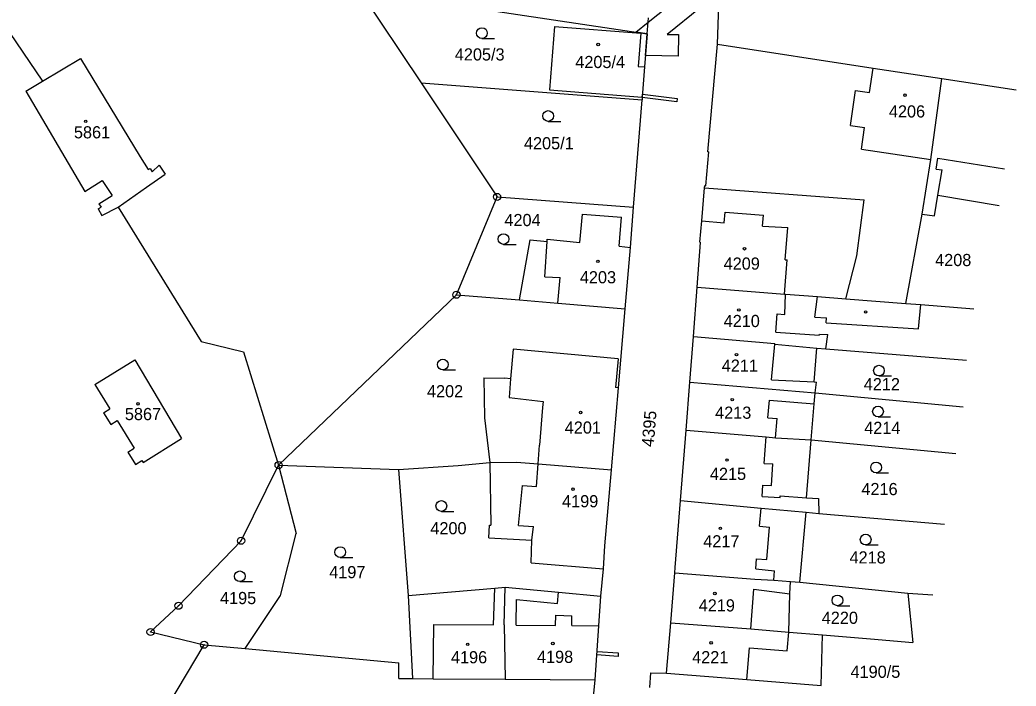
# Model space of a CAD drawing. Extents: x -735092 to -733385, y -1122435 to -1118992.
# Drawn here: x -734332.2 to -734193, y -1120070.4 to -1119977.2 of the extents above; entities that cross this region are included whole.
import ezdxf

# ---------------------------------------------------------------- set-up
doc = ezdxf.new("R2010")
doc.units = 0
for name, color, linetype in [('Vrstva 1', 7, 'Continuous'), ('Vrstva 18', 7, 'Continuous'), ('Vrstva 19', 7, 'Continuous'), ('Vrstva 25', 7, 'Continuous'), ('Vrstva 27', 7, 'Continuous'), ('Vrstva 4', 7, 'Continuous')]:
    doc.layers.add(name, color=color, linetype=linetype)

msp = doc.modelspace()

# ---------------------------------------------------------------- linework, layer by layer
at = {"layer": 'Vrstva 1'}
for points in [[(-734352.91, -1119950.56), (-734329.01, -1119985.77)], [(-734234.74, -1119980.64), (-734234.34, -1119969.65)], [(-734284.75, -1119973.09), (-734276.13, -1119986.04)], [(-734284.75, -1119973.09), (-734244.54, -1119979.16)], [(-734244.54, -1119979.16), (-734244.36, -1119976.92)], [(-734257.49, -1119978.14), (-734258.17, -1119987.02)], [(-734257.49, -1119978.14), (-734245.44, -1119979.06)], [(-734245.44, -1119979.06), (-734245.8, -1119983.74)], [(-734244.54, -1119979.16), (-734244.9, -1119983.81)], [(-734236.05, -1119995.68), (-734234.74, -1119980.64)], [(-734234.74, -1119980.64), (-734212.96, -1119983.97)], [(-734329.01, -1119985.77), (-734323.72, -1119982.6)], [(-734323.72, -1119982.6), (-734315.4, -1119996.37)], [(-734245.8, -1119983.74), (-734244.9, -1119983.81)], [(-734244.9, -1119983.81), (-734245.23, -1119988.02)], [(-734212.96, -1119983.97), (-734203.39, -1119985.4)], [(-734204.89, -1119996.75), (-734203.39, -1119985.4)], [(-734203.39, -1119985.4), (-734193, -1119987.01)], [(-734331.36, -1119987.17), (-734329.01, -1119985.77)], [(-734276.13, -1119986.04), (-734245.26, -1119988.41)], [(-734276.13, -1119986.04), (-734265.52, -1120001.98)], [(-734331.36, -1119987.17), (-734323.11, -1120001.23)], [(-734258.17, -1119987.02), (-734245.23, -1119988.02)], [(-734245.23, -1119988.02), (-734245.26, -1119988.41)], [(-734246.44, -1120003.41), (-734245.26, -1119988.41)], [(-734315.4, -1119996.37), (-734314.27, -1119998.15)], [(-734236.33, -1120000.42), (-734235.91, -1119995.69)], [(-734236.05, -1119995.68), (-734235.91, -1119995.69)], [(-734314.27, -1119998.15), (-734314, -1119997.99)], [(-734314, -1119997.99), (-734313.7, -1119998.47)], [(-734313.7, -1119998.47), (-734312.74, -1119997.56)], [(-734312.74, -1119997.56), (-734311.89, -1119998.78)], [(-734206.13, -1120004.4), (-734204.89, -1119996.75)], [(-734314.49, -1120000.61), (-734311.89, -1119998.78)], [(-734323.11, -1120001.23), (-734320.68, -1119999.7)], [(-734320.68, -1119999.7), (-734319.3, -1120001.79)], [(-734318.48, -1120003.42), (-734314.49, -1120000.61)], [(-734236.9, -1120005.32), (-734236.53, -1120000.73)], [(-734236.53, -1120000.73), (-734236.5, -1120000.4)], [(-734236.53, -1120000.73), (-734214.21, -1120002.37)], [(-734236.5, -1120000.4), (-734236.33, -1120000.42)], [(-734321.15, -1120002.94), (-734319.3, -1120001.79)], [(-734271.19, -1120015.66), (-734265.52, -1120001.98)], [(-734265.52, -1120001.98), (-734246.44, -1120003.41)], [(-734204.38, -1120004.64), (-734203.92, -1120001.75)], [(-734203.92, -1120001.75), (-734195.38, -1120003.16)], [(-734321.23, -1120003.64), (-734320.84, -1120003.43)], [(-734321.23, -1120003.64), (-734320.73, -1120004.56)], [(-734321.15, -1120002.94), (-734320.84, -1120003.43)], [(-734320.73, -1120004.56), (-734318.48, -1120003.42)], [(-734318.48, -1120003.42), (-734306.84, -1120022.19)], [(-734246.88, -1120009.04), (-734246.44, -1120003.41)], [(-734215.26, -1120010.23), (-734214.21, -1120002.37)], [(-734253.93, -1120008.34), (-734253.59, -1120004.4)], [(-734253.59, -1120004.4), (-734248.13, -1120004.8)], [(-734248.47, -1120008.88), (-734248.13, -1120004.8)], [(-734208.42, -1120016.87), (-734206.13, -1120004.4)], [(-734206.13, -1120004.4), (-734204.38, -1120004.64)], [(-734237.19, -1120008.32), (-734236.9, -1120005.32)], [(-734262.36, -1120016.39), (-734260.88, -1120007.96)], [(-734260.88, -1120007.96), (-734258.53, -1120008.19)], [(-734258.53, -1120008.19), (-734258.51, -1120007.89)], [(-734258.51, -1120007.89), (-734253.93, -1120008.34)], [(-734248.47, -1120008.88), (-734246.88, -1120009.04)], [(-734247.6, -1120017.62), (-734246.88, -1120009.04)], [(-734237.54, -1120014.59), (-734237.08, -1120008.33)], [(-734237.19, -1120008.32), (-734237.08, -1120008.33)], [(-734216.78, -1120016.23), (-734215.26, -1120010.23)], [(-734238.07, -1120021.51), (-734237.54, -1120014.59)], [(-734237.54, -1120014.59), (-734225.35, -1120015.57)], [(-734296.04, -1120039.48), (-734271.19, -1120015.66)], [(-734271.19, -1120015.66), (-734262.36, -1120016.39)], [(-734225.35, -1120015.57), (-734225.2, -1120015.58)], [(-734225.2, -1120015.58), (-734220.75, -1120015.92)], [(-734220.75, -1120015.92), (-734216.78, -1120016.23)], [(-734262.36, -1120016.39), (-734257.03, -1120016.82)], [(-734257.03, -1120016.82), (-734247.6, -1120017.62)], [(-734216.78, -1120016.23), (-734208.42, -1120016.87)], [(-734208.42, -1120016.87), (-734206.32, -1120017.04)], [(-734206.32, -1120017.04), (-734198.92, -1120017.65)], [(-734248.54, -1120028.68), (-734247.6, -1120017.62)], [(-734238.57, -1120027.87), (-734238.07, -1120021.51)], [(-734238.07, -1120021.51), (-734226.69, -1120022.46)], [(-734306.84, -1120022.19), (-734300.96, -1120023.64)], [(-734226.7, -1120022.57), (-734226.69, -1120022.46)], [(-734226.7, -1120022.57), (-734220.84, -1120023.11)], [(-734221.2, -1120027.86), (-734220.84, -1120023.11)], [(-734220.84, -1120023.11), (-734219.57, -1120023.23)], [(-734300.96, -1120023.64), (-734296.04, -1120039.48)], [(-734263.29, -1120023.29), (-734263.62, -1120027.4)], [(-734248.61, -1120024.64), (-734263.29, -1120023.29)], [(-734219.57, -1120023.23), (-734199.94, -1120024.79)], [(-734321.72, -1120028.2), (-734316.15, -1120024.74)], [(-734316.15, -1120024.74), (-734309.63, -1120035.75)], [(-734248.61, -1120024.64), (-734248.96, -1120028.64)], [(-734267.38, -1120027.26), (-734264.41, -1120027.34)], [(-734267.38, -1120027.26), (-734267.27, -1120032.87)], [(-734263.62, -1120027.4), (-734264.41, -1120027.34)], [(-734321.72, -1120028.2), (-734319.62, -1120031.59)], [(-734249.52, -1120040.12), (-734248.54, -1120028.68)], [(-734248.54, -1120028.68), (-734248.96, -1120028.64)], [(-734239.1, -1120034.61), (-734238.57, -1120027.87)], [(-734238.57, -1120027.87), (-734221.07, -1120029.38)], [(-734221.2, -1120027.86), (-734220.9, -1120027.88)], [(-734221.07, -1120029.38), (-734220.9, -1120027.88)], [(-734221.2, -1120030.9), (-734221.07, -1120029.38)], [(-734221.07, -1120029.38), (-734200.39, -1120031.34)], [(-734221.61, -1120035.93), (-734221.2, -1120030.9)], [(-734320.52, -1120032.15), (-734319.62, -1120031.59)], [(-734320.52, -1120032.15), (-734319.5, -1120033.81)], [(-734267.27, -1120032.87), (-734266.52, -1120039.14)], [(-734319.5, -1120033.81), (-734318.59, -1120033.25)], [(-734318.59, -1120033.25), (-734316.2, -1120037.11)], [(-734239.87, -1120044.42), (-734239.1, -1120034.61)], [(-734239.1, -1120034.61), (-734227.93, -1120035.55)], [(-734227.93, -1120035.55), (-734226.6, -1120035.66)], [(-734226.6, -1120035.66), (-734221.61, -1120035.93)], [(-734314.97, -1120039.1), (-734309.63, -1120035.75)], [(-734222.3, -1120044.04), (-734221.61, -1120035.93)], [(-734221.61, -1120035.93), (-734201.43, -1120037.84)], [(-734317.09, -1120037.66), (-734316.2, -1120037.11)], [(-734317.09, -1120037.66), (-734316.02, -1120039.39)], [(-734316.02, -1120039.39), (-734315.13, -1120038.84)], [(-734315.13, -1120038.84), (-734314.97, -1120039.1)], [(-734301.28, -1120050.06), (-734296.04, -1120039.48)], [(-734296.04, -1120039.48), (-734279.29, -1120040.09)], [(-734296.04, -1120039.48), (-734293.61, -1120049.04)], [(-734279.29, -1120040.09), (-734270.94, -1120039.55)], [(-734270.94, -1120039.55), (-734266.52, -1120039.14)], [(-734266.52, -1120039.14), (-734262.82, -1120039.05)], [(-734266.52, -1120039.14), (-734266.39, -1120047.9)], [(-734262.82, -1120039.05), (-734259.78, -1120039.29)], [(-734259.78, -1120039.29), (-734249.52, -1120040.12)], [(-734279.29, -1120040.09), (-734277.93, -1120057.7)], [(-734250.44, -1120050.77), (-734249.52, -1120040.12)], [(-734222.3, -1120044.04), (-734220.6, -1120044.16)], [(-734240.63, -1120053.79), (-734239.87, -1120044.42)], [(-734239.87, -1120044.42), (-734228.6, -1120045.5)], [(-734220.6, -1120044.16), (-734220.54, -1120046.24)], [(-734228.6, -1120045.5), (-734222.34, -1120046.07)], [(-734223.22, -1120055.84), (-734222.34, -1120046.07)], [(-734222.34, -1120046.07), (-734220.54, -1120046.24)], [(-734220.54, -1120046.24), (-734203.02, -1120047.74)], [(-734266.67, -1120049.64), (-734266.57, -1120047.89)], [(-734266.57, -1120047.89), (-734266.39, -1120047.9)], [(-734295.79, -1120057.71), (-734293.61, -1120049.04)], [(-734310.02, -1120059.15), (-734301.28, -1120050.06)], [(-734266.67, -1120049.64), (-734260.64, -1120049.96)], [(-734260.77, -1120053.15), (-734260.64, -1120049.96)], [(-734250.66, -1120053.98), (-734250.44, -1120050.77)], [(-734260.77, -1120053.15), (-734250.66, -1120053.98)], [(-734240.69, -1120054.53), (-734240.63, -1120053.79)], [(-734251.04, -1120057.79), (-734250.66, -1120053.98)], [(-734241.26, -1120061.55), (-734240.69, -1120054.53)], [(-734240.69, -1120054.53), (-734229.51, -1120055.41)], [(-734265.83, -1120056.68), (-734264.39, -1120056.56)], [(-734264.51, -1120061.84), (-734264.39, -1120056.56)], [(-734264.39, -1120056.56), (-734256.93, -1120057.25)], [(-734229.51, -1120055.41), (-734226.84, -1120055.59)], [(-734226.84, -1120055.59), (-734224.5, -1120055.75)], [(-734224.62, -1120057.49), (-734224.5, -1120055.75)], [(-734224.5, -1120055.75), (-734223.22, -1120055.84)], [(-734223.22, -1120055.84), (-734208.12, -1120057.37)], [(-734300.73, -1120065.14), (-734295.79, -1120057.71)], [(-734277.93, -1120057.7), (-734265.83, -1120056.68)], [(-734277.93, -1120057.7), (-734277.32, -1120069.34)], [(-734256.93, -1120057.25), (-734251.04, -1120057.79)], [(-734251.31, -1120061.94), (-734251.04, -1120057.79)], [(-734224.77, -1120062.84), (-734224.62, -1120057.49)], [(-734208.12, -1120057.37), (-734207.41, -1120064.28)], [(-734208.12, -1120057.37), (-734204.61, -1120057.62)], [(-734313.93, -1120062.82), (-734310.02, -1120059.15)], [(-734264.51, -1120061.84), (-734264.38, -1120069.42)], [(-734251.82, -1120069.5), (-734251.31, -1120061.94)], [(-734241.83, -1120068.59), (-734241.26, -1120061.55)], [(-734241.26, -1120061.55), (-734230.05, -1120062.39)], [(-734313.93, -1120062.82), (-734306.45, -1120064.6)], [(-734230.05, -1120062.39), (-734224.77, -1120062.84)], [(-734224.77, -1120062.84), (-734220.07, -1120063.23)], [(-734220.23, -1120070.31), (-734220.07, -1120063.23)], [(-734220.07, -1120063.23), (-734213.34, -1120063.79)], [(-734320.21, -1120087.78), (-734306.45, -1120064.6)], [(-734306.45, -1120064.6), (-734300.73, -1120065.14)], [(-734213.34, -1120063.79), (-734207.41, -1120064.28)], [(-734300.73, -1120065.14), (-734279.24, -1120067.15)], [(-734279.25, -1120069.33), (-734279.24, -1120067.15)], [(-734244.19, -1120070.57), (-734244.01, -1120068.53)], [(-734244.01, -1120068.53), (-734241.83, -1120068.59)], [(-734241.83, -1120068.59), (-734230.6, -1120069.45)], [(-734279.25, -1120069.33), (-734277.32, -1120069.34)], [(-734277.32, -1120069.34), (-734274.44, -1120069.35)], [(-734274.44, -1120069.35), (-734264.38, -1120069.42)], [(-734264.38, -1120069.42), (-734251.82, -1120069.5)], [(-734252.41, -1120075.73), (-734251.82, -1120069.5)], [(-734230.6, -1120069.45), (-734220.23, -1120070.31)]]:
    msp.add_lwpolyline(points, dxfattribs=at)
at = {"layer": 'Vrstva 25'}
for points in [[(-734267.63, -1119979.82), (-734265.88, -1119979.82)], [(-734258.38, -1119991.41), (-734256.63, -1119991.41)], [(-734264.62, -1120008.62), (-734262.87, -1120008.62)], [(-734273.09, -1120026.17), (-734271.34, -1120026.17)], [(-734212.16, -1120027.02), (-734210.41, -1120027.02)], [(-734212.29, -1120032.73), (-734210.54, -1120032.73)], [(-734212.56, -1120040.56), (-734210.81, -1120040.56)], [(-734273.3, -1120045.95), (-734271.55, -1120045.95)], [(-734214.02, -1120050.65), (-734212.27, -1120050.65)], [(-734287.43, -1120052.4), (-734285.68, -1120052.4)], [(-734301.46, -1120055.78), (-734299.71, -1120055.78)], [(-734217.96, -1120059.15), (-734216.21, -1120059.15)]]:
    msp.add_lwpolyline(points, dxfattribs=at)
for centre, radius in [((-734267.63, -1119979.07), 0.75), ((-734251.39, -1119980.67), 0.175), ((-734208.51, -1119987.75), 0.175), ((-734258.38, -1119990.66), 0.75), ((-734322.99, -1119991.42), 0.175), ((-734265.52, -1120001.98), 0.499), ((-734265.52, -1120001.98), 0.0314), ((-734264.62, -1120007.87), 0.75), ((-734230.94, -1120009.23), 0.175), ((-734251.43, -1120010.98), 0.175), ((-734271.19, -1120015.66), 0.5), ((-734271.19, -1120015.66), 0.032), ((-734231.73, -1120017.79), 0.175), ((-734214.02, -1120018.06), 0.175), ((-734232.07, -1120024.03), 0.175), ((-734273.09, -1120025.42), 0.75), ((-734212.16, -1120026.27), 0.75), ((-734315.68, -1120030.91), 0.175), ((-734232.66, -1120030.34), 0.175), ((-734212.29, -1120031.98), 0.75), ((-734253.84, -1120032.12), 0.175), ((-734296.04, -1120039.48), 0.5), ((-734296.04, -1120039.48), 0.032), ((-734233.39, -1120038.77), 0.175), ((-734212.56, -1120039.81), 0.75), ((-734254.9, -1120042.85), 0.175), ((-734273.3, -1120045.2), 0.75), ((-734234.32, -1120048.33), 0.175), ((-734301.28, -1120050.06), 0.5), ((-734214.02, -1120049.9), 0.75), ((-734301.28, -1120050.06), 0.032), ((-734287.43, -1120051.65), 0.75), ((-734301.46, -1120055.03), 0.75), ((-734235.08, -1120057.43), 0.175), ((-734217.96, -1120058.4), 0.75), ((-734310.02, -1120059.15), 0.5), ((-734310.02, -1120059.15), 0.032), ((-734313.93, -1120062.82), 0.5), ((-734313.93, -1120062.82), 0.032), ((-734306.45, -1120064.6), 0.5), ((-734306.45, -1120064.6), 0.032), ((-734269.62, -1120064.55), 0.175), ((-734257.72, -1120064.43), 0.175), ((-734235.61, -1120064.33), 0.175)]:
    msp.add_circle(centre, radius, dxfattribs=at)
at = {"layer": 'Vrstva 27'}
for points in [[(-734244.41, -1119977.53), (-734239.02, -1119973.21)], [(-734237.14, -1119975.55), (-734241.77, -1119979.26)], [(-734246.14, -1119978.92), (-734244.41, -1119977.53)], [(-734244.54, -1119979.16), (-734246.14, -1119978.92)], [(-734244.78, -1119982.22), (-734244.54, -1119979.16)], [(-734241.77, -1119979.26), (-734240.16, -1119979.28)], [(-734240.16, -1119979.28), (-734240.2, -1119982.28)], [(-734240.2, -1119982.28), (-734244.78, -1119982.22)], [(-734245.2, -1119987.59), (-734240.34, -1119988.2), (-734240.4, -1119988.7), (-734245.24, -1119988.09), (-734245.2, -1119987.59)], [(-734251.55, -1120065.53), (-734248.58, -1120065.73), (-734248.61, -1120066.23), (-734251.59, -1120066.03), (-734251.55, -1120065.53)]]:
    msp.add_lwpolyline(points, dxfattribs=at)
at = {"layer": 'Vrstva 4'}
for points in [[(-734213.46, -1119987.37), (-734212.96, -1119983.97)], [(-734216.12, -1119992), (-734215.42, -1119987.09)], [(-734215.42, -1119987.09), (-734213.46, -1119987.37)], [(-734216.12, -1119992), (-734214.18, -1119992.28)], [(-734214.62, -1119995.32), (-734214.18, -1119992.28)], [(-734214.62, -1119995.32), (-734204.89, -1119996.75)], [(-734204.18, -1119998.08), (-734203.94, -1119996.56)], [(-734203.94, -1119996.56), (-734194.63, -1119998.05)], [(-734204.18, -1119998.08), (-734203.35, -1119998.21)], [(-734203.92, -1120001.75), (-734203.35, -1119998.21)], [(-734233.78, -1120005.62), (-734233.66, -1120004.12)], [(-734233.66, -1120004.12), (-734228.29, -1120004.55)], [(-734228.41, -1120006.05), (-734228.29, -1120004.55)], [(-734236.9, -1120005.32), (-734233.78, -1120005.62)], [(-734228.41, -1120006.05), (-734224.88, -1120006.25)], [(-734225.24, -1120010.77), (-734224.88, -1120006.25)], [(-734258.83, -1120013.14), (-734258.53, -1120008.19)], [(-734225.35, -1120015.57), (-734224.98, -1120010.79)], [(-734225.24, -1120010.77), (-734224.98, -1120010.79)], [(-734258.83, -1120013.14), (-734256.69, -1120013.27)], [(-734257.03, -1120016.82), (-734256.69, -1120013.27)], [(-734225.31, -1120018.43), (-734225.2, -1120015.58)], [(-734221.11, -1120018.78), (-734220.75, -1120015.92)], [(-734206.65, -1120020.42), (-734206.32, -1120017.04)], [(-734226.58, -1120020.88), (-734226.39, -1120018.35)], [(-734226.39, -1120018.35), (-734225.31, -1120018.43)], [(-734221.11, -1120018.78), (-734219.49, -1120018.88)], [(-734219.54, -1120019.58), (-734219.49, -1120018.88)], [(-734219.54, -1120019.58), (-734206.65, -1120020.42)], [(-734226.58, -1120020.88), (-734220.49, -1120021.33)], [(-734220.49, -1120021.33), (-734220.48, -1120021.18)], [(-734220.48, -1120021.18), (-734219.29, -1120021.24)], [(-734219.57, -1120023.23), (-734219.29, -1120021.24)], [(-734227.17, -1120027.55), (-734226.7, -1120022.57)], [(-734263.62, -1120027.4), (-734263.83, -1120030.04), (-734259.08, -1120030.6)], [(-734227.17, -1120027.55), (-734221.2, -1120027.86)], [(-734259.15, -1120031.44), (-734259.57, -1120036.7)], [(-734259.08, -1120030.6), (-734259.15, -1120031.44)], [(-734227.68, -1120032.87), (-734227.44, -1120030.39)], [(-734227.44, -1120030.39), (-734221.2, -1120030.9)], [(-734227.68, -1120032.87), (-734226.37, -1120032.98)], [(-734226.6, -1120035.66), (-734226.37, -1120032.98)], [(-734228.18, -1120039.24), (-734227.93, -1120035.55)], [(-734259.78, -1120039.29), (-734259.57, -1120036.7)], [(-734260.01, -1120042.48), (-734259.78, -1120039.29)], [(-734228.18, -1120039.24), (-734226.98, -1120039.32)], [(-734227.19, -1120042.35), (-734226.98, -1120039.32)], [(-734262.53, -1120047.94), (-734261.98, -1120042.34)], [(-734261.98, -1120042.34), (-734260.01, -1120042.48)], [(-734228.49, -1120043.86), (-734228.38, -1120042.27)], [(-734228.38, -1120042.27), (-734227.19, -1120042.35)], [(-734228.49, -1120043.86), (-734225.97, -1120044.03)], [(-734225.97, -1120044.03), (-734225.95, -1120043.78)], [(-734225.95, -1120043.78), (-734222.3, -1120044.04)], [(-734228.83, -1120048.01), (-734228.6, -1120045.5)], [(-734262.53, -1120047.94), (-734260.41, -1120048.09)], [(-734260.64, -1120049.96), (-734260.41, -1120048.09)], [(-734228.83, -1120048.01), (-734227.47, -1120048.14)], [(-734227.82, -1120052.67), (-734227.47, -1120048.14)], [(-734229.38, -1120054.01), (-734229.25, -1120052.57)], [(-734229.25, -1120052.57), (-734227.82, -1120052.67)], [(-734229.38, -1120054.01), (-734226.75, -1120054.25)], [(-734226.84, -1120055.59), (-734226.75, -1120054.25)], [(-734266.03, -1120061.83), (-734265.83, -1120056.68)], [(-734257.07, -1120058.83), (-734256.93, -1120057.25)], [(-734230.05, -1120062.39), (-734229.62, -1120056.81)], [(-734229.62, -1120056.81), (-734224.62, -1120057.49)], [(-734262.83, -1120061.85), (-734262.8, -1120058.29)], [(-734262.8, -1120058.29), (-734257.07, -1120058.83)], [(-734257.33, -1120061.89), (-734257.32, -1120060.48)], [(-734257.32, -1120060.48), (-734255.08, -1120060.57)], [(-734255.09, -1120061.91), (-734255.08, -1120060.57)], [(-734274.44, -1120069.35), (-734274.36, -1120061.76)], [(-734274.36, -1120061.76), (-734266.03, -1120061.83)], [(-734262.83, -1120061.85), (-734257.33, -1120061.89)], [(-734255.09, -1120061.91), (-734251.31, -1120061.94)], [(-734225, -1120065.44), (-734224.77, -1120062.84)], [(-734230.6, -1120069.45), (-734230.26, -1120065.03)], [(-734230.26, -1120065.03), (-734225, -1120065.44)]]:
    msp.add_lwpolyline(points, dxfattribs=at)

# ---------------------------------------------------------------- texts
at = {"layer": 'Vrstva 18'}
for s, p in [('4205/3', (-734271.42, -1119982.9)), ('4205/1', (-734261.76, -1119995.32)), ('4204', (-734264.49, -1120006.06)), ('4208', (-734204.31, -1120011.65)), ('4212', (-734214.28, -1120029.01)), ('4202', (-734275.31, -1120030)), ('4214', (-734214.22, -1120035.12)), ('4216', (-734214.61, -1120043.68)), ('4200', (-734274.84, -1120049.16)), ('4218', (-734216.27, -1120053.24)), ('4197', (-734288.97, -1120055.3)), ('4195', (-734304.23, -1120058.92)), ('4220', (-734220.15, -1120061.68)), ('4190/5', (-734216.13, -1120069.23))]:
    msp.add_text(s, height=1.7, dxfattribs=at).set_placement(p)
msp.add_text('4395', height=1.7, rotation=85.20068, dxfattribs=at).set_placement((-734243.642, -1120036.984))
at = {"layer": 'Vrstva 19'}
for s, p in [('4205/4', (-734254.588, -1119983.96)), ('4206', (-734210.77, -1119990.87)), ('5861', (-734324.64, -1119993.79)), ('4209', (-734233.86, -1120012.15)), ('4203', (-734253.95, -1120014.06)), ('4210', (-734233.86, -1120020.18)), ('4211', (-734234.12, -1120026.42)), ('5867', (-734317.52, -1120033.19)), ('4213', (-734235.05, -1120033)), ('4201', (-734256.06, -1120035.08)), ('4215', (-734235.78, -1120041.56)), ('4199', (-734256.43, -1120045.38)), ('4217', (-734236.71, -1120050.99)), ('4219', (-734237.34, -1120059.95)), ('4196', (-734271.96, -1120067.2)), ('4198', (-734259.94, -1120067.14)), ('4221', (-734238.26, -1120067.19))]:
    msp.add_text(s, height=1.7, dxfattribs=at).set_placement(p)

doc.saveas('drawing.dxf')
